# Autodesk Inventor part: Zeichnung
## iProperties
Title: Zeichnung
Author: Schneider
Revision Number: 00
Created: 2002-08
Part Number: Z46_TSch
Material: Standard
Document SubType Name: Modellieren
Designer: Schneider
Company: Kunde
Breite: 1,000 mm
Höhe: 1,000 mm
Tiefe: 1,000 mm
Breite_1: 1,000 mm
Höhe_1: 1,000 mm
Tiefe_1: 1,000 mm
Control State: 0
Master: False
Checked Out: False
Last Check In By: KSO_Schneider
Last Check In Date: 2002-08-16
PropertySet Name: Design Tracking Control
Shininess: 20.0
Angle Display Precision: 2
Document Length Units: 11269
Document Angle Units: 11283
Document Time Units: 11279
Document Mass Units: 11290
Document Length Units Precision: 3
Document Angle Units Precision: 2
Compacted: False
PropertySet Name: _Private Model Information
Density: 0.0
Volumn: 0.0
Area: 0.0
PropertySet Name: Model Information
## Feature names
1. Abgeleiteter Körper1 [Tagging]
